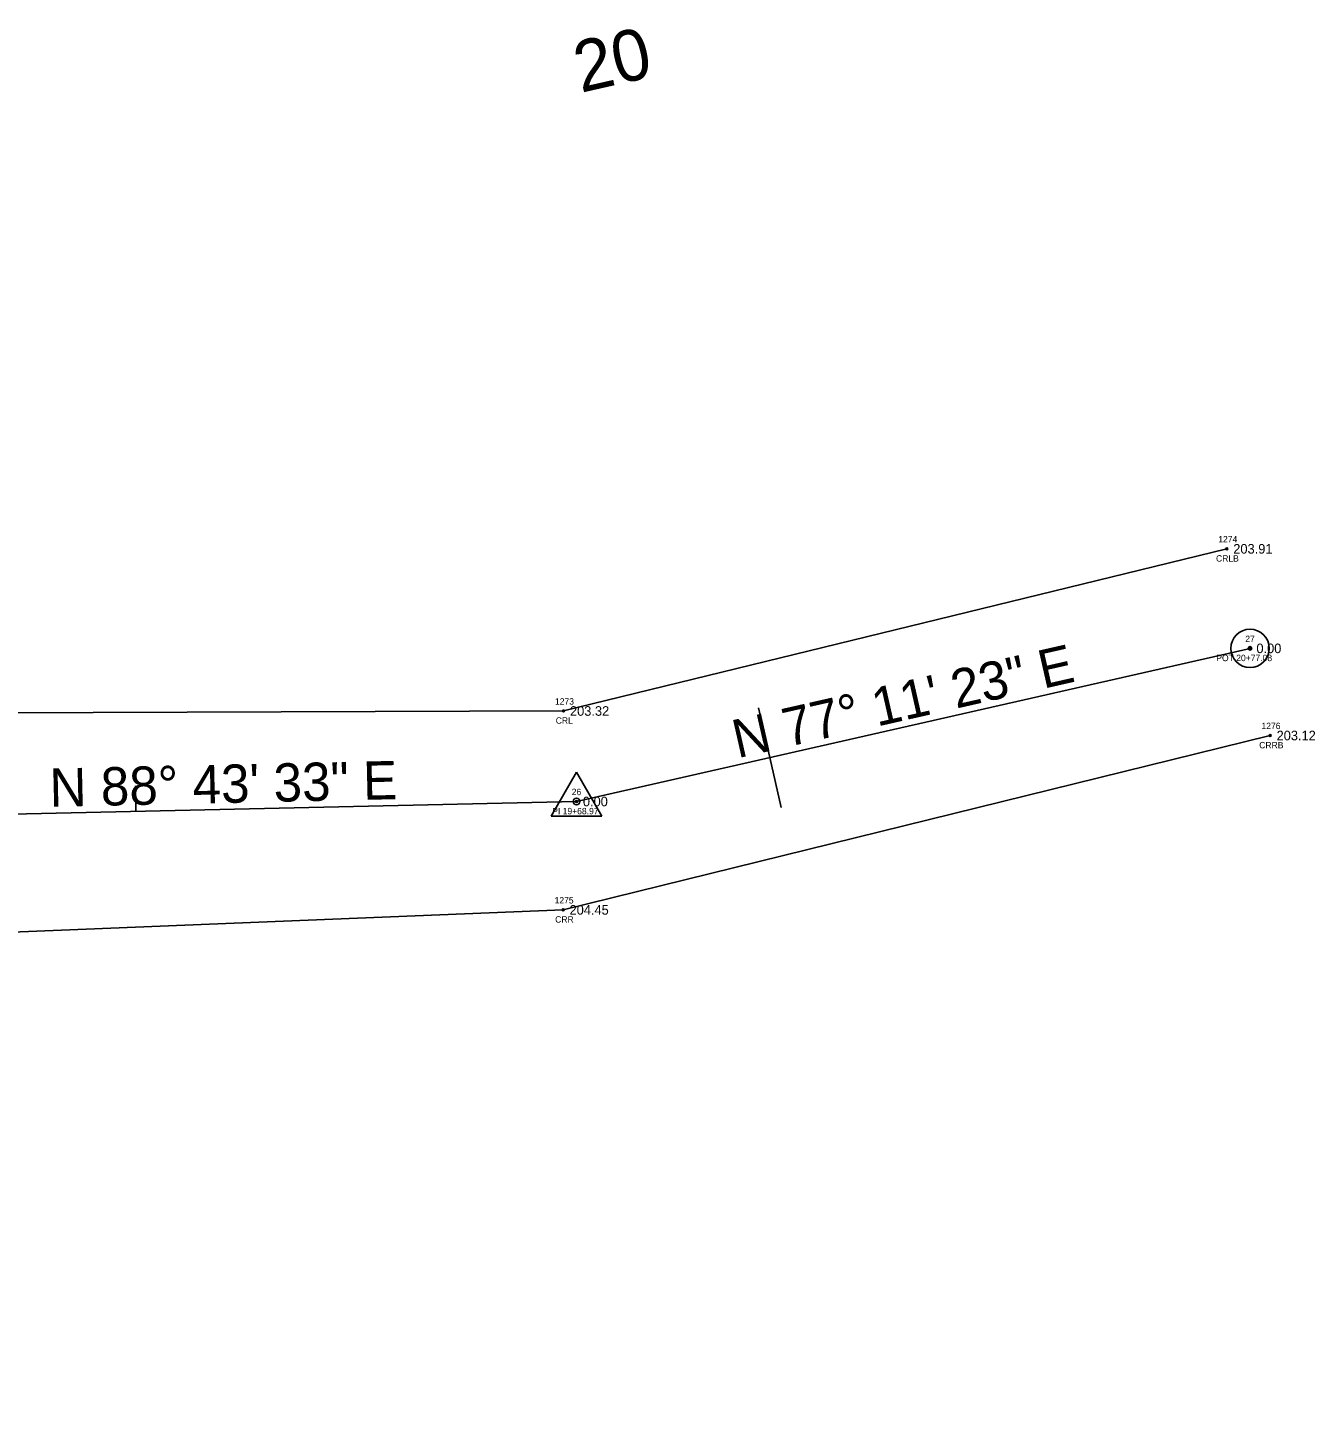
# Model space of a CAD drawing. Extents: x 2259948 to 2261336, y 1064647 to 1065986.
# Drawn here: x 2261097.4 to 2261298.9, y 1065077.8 to 1065295.7 of the extents above; entities that cross this region are included whole.
import ezdxf

# ---------------------------------------------------------------- set-up
doc = ezdxf.new("R2010")
doc.units = 0
for name, color, linetype in [('RD_EX_H2O', 7, 'Continuous'), ('RD_EX_H2O_txCode', 7, 'Continuous'), ('RD_EX_TX_H2O_ELEV', 7, 'Continuous'), ('RD_HC_Cl', 7, 'Continuous'), ('RD_HC_Data', 7, 'Continuous'), ('RD_HC_Data_Tic', 7, 'Continuous'), ('RD_HC_Survey_ELEV', 7, 'Continuous'), ('RD_HC_TX_Sta50', 7, 'Continuous'), ('RD_HC_txCode', 7, 'Continuous'), ('RD_SMD_Locator', 7, 'Continuous')]:
    doc.layers.add(name, color=color, linetype=linetype)

msp = doc.modelspace()

# ---------------------------------------------------------------- linework, layer by layer
at = {"layer": 'RD_EX_H2O'}
for points in [[(2260885.41, 1065184.64), (2260936, 1065235.25), (2260958.14, 1065240.42), (2260996.14, 1065264.19), (2261041.44, 1065253.62), (2261057.19, 1065228.35), (2261051.93, 1065209.3), (2261057.29, 1065196.01), (2261078.07, 1065188.45), (2261181.25, 1065188.78), (2261285.07, 1065214.16)], [(2260835.04, 1065077.78), (2260839.45, 1065081.34), (2260836.25, 1065093.94), (2260905.11, 1065142.54), (2260939.15, 1065178.33), (2260943.42, 1065185.77), (2260976.49, 1065206.39), (2260992.26, 1065206.09), (2261009.06, 1065194.12), (2261027.03, 1065166.48), (2261074.3, 1065153.35), (2261181.18, 1065157.65), (2261291.85, 1065184.94)]]:
    msp.add_lwpolyline(points, dxfattribs=at)
at = {"layer": 'RD_HC_Cl'}
for p, q in [((2261183.27, 1065174.61), (2261288.69, 1065198.58)), ((2261074.43, 1065172.19), (2261183.27, 1065174.61))]:
    msp.add_line(p, q, dxfattribs=at)
at = {"layer": 'RD_HC_Data'}
for p, q in [((2261179.3, 1065172.31), (2261183.27, 1065179.19)), ((2261183.27, 1065179.19), (2261187.24, 1065172.31)), ((2261179.3, 1065172.31), (2261187.24, 1065172.31))]:
    msp.add_line(p, q, dxfattribs=at)
for centre, radius in [((2261288.69, 1065198.58), 3), ((2261288.69, 1065198.58), 0.282), ((2261183.27, 1065174.61), 0.529)]:
    msp.add_circle(centre, radius, dxfattribs=at)
at = {"layer": 'RD_HC_Data_Tic'}
for p, q in [((2261213.53, 1065181.49), (2261211.75, 1065189.29)), ((2261213.53, 1065181.49), (2261215.3, 1065173.69)), ((2261114.31, 1065173.07), (2261114.23, 1065177.07))]:
    msp.add_line(p, q, dxfattribs=at)
at = {"layer": 'RD_SMD_Locator'}
for centre in [(2261285.07, 1065214.16), (2261288.69, 1065198.58), (2261181.25, 1065188.78), (2261291.85, 1065184.94), (2261183.27, 1065174.61), (2261181.18, 1065157.65)]:
    msp.add_circle(centre, 0.15, dxfattribs=at)

# ---------------------------------------------------------------- texts
at = {"layer": 'RD_EX_H2O_txCode'}
for s, p in [('1274', (2261283.72, 1065215.16)), ('CRLB', (2261283.37, 1065212.16)), ('1273', (2261179.9, 1065189.78)), ('CRL', (2261180.02, 1065186.78)), ('1276', (2261290.48, 1065185.94)), ('CRRB', (2261290.13, 1065182.94)), ('1275', (2261179.84, 1065158.65)), ('CRR', (2261179.93, 1065155.65))]:
    msp.add_text(s, height=1, dxfattribs=at).set_placement(p)
at = {"layer": 'RD_EX_TX_H2O_ELEV'}
for s, p in [('203.91', (2261286.07, 1065213.41)), ('203.32', (2261182.25, 1065188.03)), ('203.12', (2261292.85, 1065184.19)), ('204.45', (2261182.18, 1065156.9))]:
    msp.add_text(s, height=1.5, dxfattribs=at).set_placement(p)
at = {"layer": 'RD_HC_Data'}
for s, rotation, p in [('N 77%%d 11\' 23" E', 12.8104, (2261208.47, 1065181.36)), ('N 88%%d 43\' 33" E', 1.2741, (2261100.85, 1065173.77))]:
    msp.add_text(s, height=6, rotation=rotation, dxfattribs=at).set_placement(p)
at = {"layer": 'RD_HC_Survey_ELEV'}
for p in [(2261289.69, 1065197.83), (2261184.27, 1065173.86)]:
    msp.add_text('0.00', height=1.5, dxfattribs=at).set_placement(p)
at = {"layer": 'RD_HC_TX_Sta50'}
msp.add_text('20', height=8, rotation=12.8104, dxfattribs=at).set_placement((2261183.93, 1065285.51))
at = {"layer": 'RD_HC_txCode'}
for s, p in [('27', (2261287.95, 1065199.58)), ('POT 20+77.08', (2261283.41, 1065196.58)), ('26', (2261182.52, 1065175.61)), ('PI 19+68.97', (2261179.47, 1065172.61))]:
    msp.add_text(s, height=1, dxfattribs=at).set_placement(p)

doc.saveas('drawing.dxf')
